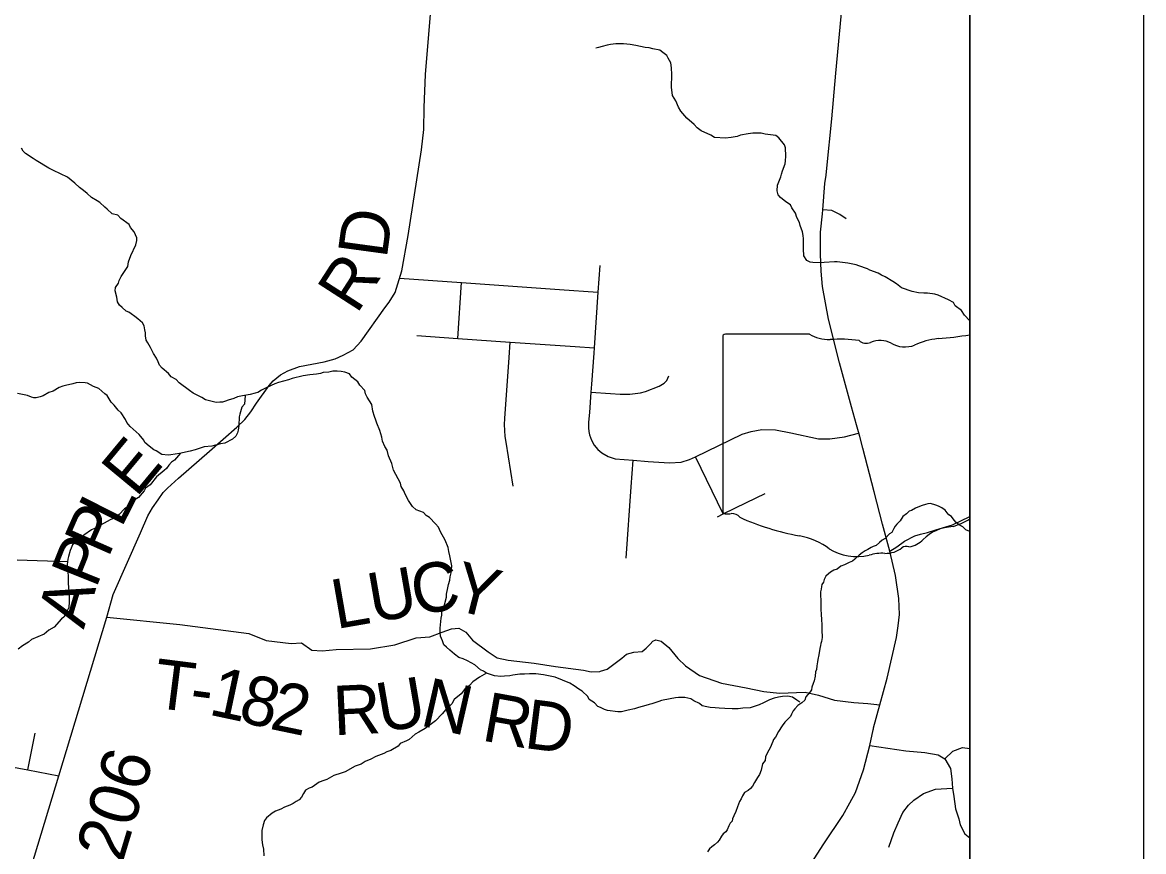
# Model space of a CAD drawing. Extents: x 0 to 34, y 0 to 22.
# Drawn here: x 8.355 to 9, y 14.464 to 14.941 of the extents above; entities that cross this region are included whole.
import ezdxf

# ---------------------------------------------------------------- set-up
doc = ezdxf.new("R2010")
doc.units = 0
for name, color, linetype in [('GM_X_Corporation', 7, 'Continuous'), ('GM_X_Corporation_Text', 7, 'Continuous'), ('GM_X_Minor_River', 7, 'Continuous'), ('GM_X_State_Location', 7, 'Continuous'), ('GM_X_State_Route', 7, 'Continuous'), ('GM_X_Township_Road', 7, 'Continuous'), ('GM_X_Township_Road_Text', 7, 'Continuous'), ('SH_Cut_Line', 7, 'Continuous'), ('SH_Data', 7, 'Continuous')]:
    doc.layers.add(name, color=color, linetype=linetype)

msp = doc.modelspace()

# ---------------------------------------------------------------- linework, layer by layer
at = {"layer": 'GM_X_Corporation'}
msp.add_lwpolyline([(8.31297, 14.1), (8.9, 14.1), (8.9, 17.02104)], dxfattribs=at)
at = {"layer": 'GM_X_Corporation_Text'}
for p, q in [((8.8078, 14.76211), (8.75951, 14.76211)), ((8.9, 14.65569), (8.9, 14.76171)), ((8.75792, 14.76037), (8.75792, 14.66033))]:
    msp.add_line(p, q, dxfattribs=at)
for centre, major_axis, start_param, end_param in [((8.75981, 14.7606), (0.00191, 0), 1.727492, 3.291633), ((8.81929, 14.77372), (0.01852, 0), 4.042888, 4.731792), ((8.86401, 14.89852), (0.17476, 0), 4.814394, 4.919827), ((8.82543, 14.70593), (0.06648, 0), 1.404758, 1.657859), ((8.84052, 14.76112), (0.00534, 0), 3.836095, 5.185415), ((8.84837, 14.74955), (0.01111, 0), 0.950623, 2.079405), ((8.8627, 14.76541), (0.01336, 0), 4.08156, 5.145723), ((8.8863, 14.73155), (0.03516, 0), 1.699012, 2.107814), ((8.75982, 14.66011), (0.00193, 0), 2.993084, 4.5083), ((8.76011, 14.67034), (0.0147, 0), 4.665946, 4.897461), ((8.76312, 14.65455), (0.0053, 0), 0.519207, 1.627899), ((8.83003, 14.74445), (0.1262, 0), 4.195997, 4.488961), ((8.8738, 14.68368), (0.04371, 0), 5.101753, 5.355196), ((8.79241, 14.61537), (0.03949, 0), 0.823519, 1.323587), ((8.89223, 14.63223), (0.02394, 0), 1.647645, 2.488434), ((8.85142, 14.64656), (0.01335, 0), 4.691044, 5.507374), ((8.8635, 14.63687), (0.00376, 0), 1.147584, 2.315152), ((8.8619, 14.65063), (0.01412, 0), 4.937069, 5.64225), ((8.83512, 14.65406), (0.02506, 0), 4.026481, 4.996735), ((8.84959, 14.61946), (0.02059, 0), 1.495662, 1.94098)]:
    msp.add_ellipse(centre, major_axis=major_axis, ratio=0.8, start_param=start_param, end_param=end_param, dxfattribs=at)
at = {"layer": 'GM_X_Minor_River'}
for points in [[(8.70473, 14.92874), (8.70094, 14.92919), (8.69637, 14.92908), (8.69332, 14.92875), (8.69142, 14.92841), (8.68855, 14.92751), (8.68645, 14.92698), (8.68493, 14.92662)], [(8.9, 14.76972), (8.89695, 14.77288), (8.89528, 14.77557), (8.89172, 14.7783), (8.89061, 14.78022), (8.88779, 14.78179), (8.88194, 14.78456), (8.87986, 14.78497), (8.87568, 14.78562), (8.87359, 14.78565), (8.87056, 14.7859), (8.86695, 14.78653), (8.86072, 14.78873), (8.85791, 14.79106), (8.85584, 14.79224), (8.85132, 14.79498), (8.84925, 14.79597), (8.84736, 14.79714), (8.84264, 14.79894), (8.84113, 14.79953), (8.83622, 14.80133), (8.83471, 14.80193), (8.82997, 14.80296), (8.82371, 14.80364), (8.82219, 14.80367), (8.81629, 14.8032), (8.8142, 14.80305), (8.80983, 14.80332), (8.80831, 14.80353), (8.80624, 14.80433), (8.80457, 14.80702), (8.80445, 14.81121), (8.80436, 14.81691), (8.8042, 14.81882), (8.80385, 14.82091), (8.80239, 14.82455), (8.80204, 14.82627), (8.80057, 14.82915), (8.79985, 14.83163), (8.79762, 14.83471), (8.79689, 14.83644), (8.79426, 14.83819), (8.79107, 14.84072), (8.78977, 14.84226), (8.78923, 14.84456), (8.78948, 14.84778), (8.79127, 14.8525), (8.79168, 14.85402), (8.79228, 14.8561), (8.79387, 14.86006), (8.79409, 14.86177), (8.79432, 14.86443), (8.79402, 14.86919), (8.79348, 14.87091), (8.79013, 14.87496), (8.78844, 14.87632), (8.78237, 14.87719), (8.78009, 14.87761), (8.77516, 14.87769), (8.77249, 14.87736), (8.7681, 14.87649), (8.76619, 14.87576), (8.76276, 14.87525), (8.75952, 14.87474), (8.75325, 14.87523), (8.751, 14.8766), (8.74552, 14.87898), (8.74327, 14.88073), (8.74159, 14.88266), (8.73728, 14.88635), (8.73393, 14.8904), (8.73245, 14.8927), (8.73099, 14.89634), (8.72895, 14.89942), (8.72846, 14.90418), (8.72858, 14.9114), (8.72845, 14.91521), (8.72812, 14.91807), (8.72646, 14.92076), (8.72572, 14.92229), (8.72347, 14.92404), (8.72178, 14.9254), (8.7178, 14.92623), (8.71553, 14.92684), (8.71326, 14.92707), (8.70795, 14.92812), (8.70473, 14.92874)], [(8.40675, 14.83133), (8.40394, 14.83404), (8.40244, 14.83502), (8.39963, 14.83773), (8.39813, 14.83871), (8.39493, 14.84066), (8.39231, 14.84299), (8.39025, 14.84474), (8.388, 14.84649), (8.38519, 14.84901), (8.38106, 14.85232), (8.37295, 14.85626), (8.37031, 14.85764), (8.36297, 14.86195), (8.36128, 14.86312), (8.35696, 14.86605), (8.35546, 14.86741), (8.35454, 14.86913)], [(8.57714, 14.66633), (8.57531, 14.66998), (8.57458, 14.67189), (8.57291, 14.67439), (8.57256, 14.6763), (8.57127, 14.67879), (8.5685, 14.68379), (8.56762, 14.68761), (8.5656, 14.69201), (8.5649, 14.69526), (8.5636, 14.69737), (8.56232, 14.70044), (8.56179, 14.70273), (8.56071, 14.70655), (8.55907, 14.71076), (8.55834, 14.71249), (8.55762, 14.71459), (8.55672, 14.71765), (8.55602, 14.72165), (8.55343, 14.72569), (8.55251, 14.72761), (8.55216, 14.72952), (8.54918, 14.73261), (8.54807, 14.73453), (8.54469, 14.73726), (8.5432, 14.73918), (8.54056, 14.74018), (8.53848, 14.7406), (8.5362, 14.74083), (8.53372, 14.74068), (8.53143, 14.74015), (8.5282, 14.74002), (8.52648, 14.73948), (8.52419, 14.73895), (8.52038, 14.73863), (8.51657, 14.73813), (8.51027, 14.73653), (8.50817, 14.73581), (8.50244, 14.7342), (8.50034, 14.73347), (8.49823, 14.73256), (8.49536, 14.73109), (8.49267, 14.72981), (8.49056, 14.72851), (8.48903, 14.72816), (8.48617, 14.72726), (8.48178, 14.72657), (8.47892, 14.72606), (8.47681, 14.72495), (8.47338, 14.72406), (8.47185, 14.72352), (8.47013, 14.72298), (8.4686, 14.72281), (8.46651, 14.72266), (8.46046, 14.72429), (8.45839, 14.72566), (8.4533, 14.72803), (8.45123, 14.72958), (8.44522, 14.73406), (8.44354, 14.736), (8.44072, 14.73757), (8.43923, 14.7393), (8.43548, 14.74241), (8.43399, 14.74415), (8.43326, 14.74606), (8.43215, 14.74817), (8.43049, 14.75087), (8.42884, 14.75432), (8.42717, 14.75701), (8.42625, 14.75855), (8.42591, 14.76102), (8.42594, 14.76273), (8.42559, 14.76445), (8.42524, 14.76674), (8.42413, 14.76847), (8.42151, 14.7708), (8.41982, 14.77216), (8.41776, 14.77372), (8.41625, 14.77469), (8.41474, 14.77529), (8.4125, 14.77742), (8.411, 14.77878), (8.40989, 14.7807), (8.40937, 14.78337), (8.40848, 14.787), (8.4087, 14.7889), (8.41045, 14.79134), (8.41086, 14.79285), (8.41184, 14.79512), (8.41574, 14.80094), (8.41617, 14.8036), (8.41756, 14.80737), (8.42032, 14.81341), (8.42094, 14.81587), (8.42096, 14.81739), (8.41931, 14.82084), (8.41726, 14.82335), (8.41653, 14.82507), (8.41165, 14.82858), (8.40997, 14.83051), (8.40675, 14.83133)], [(8.48331, 14.72681), (8.48284, 14.7218), (8.48129, 14.71993), (8.48009, 14.71596), (8.47987, 14.71444), (8.4796, 14.7095), (8.47917, 14.70685), (8.47877, 14.70533), (8.47797, 14.70325), (8.47604, 14.70158), (8.47163, 14.69937), (8.46915, 14.69885), (8.464, 14.69761), (8.45962, 14.69711), (8.45446, 14.69549), (8.4516, 14.69478), (8.44549, 14.69337), (8.44053, 14.6925), (8.43901, 14.69234), (8.43522, 14.69279), (8.43202, 14.69494), (8.4307, 14.69553), (8.42807, 14.69767), (8.42545, 14.69962), (8.4249, 14.70096), (8.42229, 14.70424), (8.41705, 14.70889), (8.41519, 14.7112), (8.41445, 14.71293), (8.41186, 14.71678), (8.41017, 14.71833), (8.40794, 14.72122), (8.40626, 14.72296), (8.40385, 14.72681), (8.40254, 14.72778), (8.39898, 14.7307), (8.39595, 14.73189), (8.39257, 14.73385), (8.39124, 14.73406), (8.38801, 14.73431), (8.3861, 14.73396), (8.38419, 14.73343), (8.37981, 14.73255), (8.37828, 14.73201), (8.37618, 14.73129), (8.37272, 14.72926), (8.37024, 14.72854), (8.36697, 14.7265), (8.36525, 14.72597), (8.36296, 14.72543), (8.36163, 14.72546), (8.36031, 14.72586), (8.35804, 14.72666), (8.35236, 14.7279)], [(8.4461, 14.69351), (8.44257, 14.68943), (8.44084, 14.68832), (8.43929, 14.68663), (8.43793, 14.68475), (8.43658, 14.68364), (8.43234, 14.67991), (8.42865, 14.67541), (8.42595, 14.67337), (8.42517, 14.67186), (8.42187, 14.66811), (8.41995, 14.66682), (8.41666, 14.66326), (8.41378, 14.6616), (8.41068, 14.65823), (8.4078, 14.65619), (8.40569, 14.65528), (8.40396, 14.65417), (8.39994, 14.65215), (8.39667, 14.65011), (8.39495, 14.64938), (8.39053, 14.64642), (8.38898, 14.64473), (8.38397, 14.64083), (8.38318, 14.63894), (8.38258, 14.63762), (8.38157, 14.63402), (8.38117, 14.63251), (8.38093, 14.62947), (8.38106, 14.62624), (8.38139, 14.62319), (8.38151, 14.619), (8.38165, 14.61615), (8.38181, 14.61424), (8.38192, 14.60968), (8.38208, 14.60796), (8.38184, 14.60474), (8.38105, 14.60323), (8.3789, 14.59927), (8.37755, 14.59816), (8.37329, 14.59348), (8.3704, 14.59163), (8.36771, 14.58939), (8.36043, 14.58629), (8.35869, 14.58479), (8.35524, 14.58276), (8.35273, 14.58072)], [(8.80235, 14.55036), (8.80065, 14.55134), (8.79802, 14.5531), (8.79537, 14.55372), (8.79233, 14.55358), (8.79004, 14.55324), (8.78756, 14.55253), (8.78488, 14.55162), (8.78143, 14.54997), (8.77894, 14.54868), (8.77378, 14.54706), (8.76959, 14.54676), (8.76673, 14.54643), (8.76331, 14.54649), (8.75913, 14.54656), (8.75591, 14.54681), (8.75363, 14.54704), (8.75078, 14.54728), (8.74888, 14.5475), (8.74604, 14.54812), (8.74455, 14.54948), (8.74134, 14.55106), (8.73965, 14.55223), (8.73605, 14.55305), (8.73244, 14.55293), (8.73072, 14.55277), (8.72767, 14.55225), (8.72271, 14.5512), (8.72118, 14.55065), (8.71717, 14.54939), (8.71564, 14.54885), (8.71373, 14.54831), (8.70953, 14.54724), (8.70724, 14.54652), (8.70361, 14.54564), (8.6998, 14.54475), (8.69752, 14.54479), (8.69163, 14.54547), (8.68993, 14.54607), (8.68767, 14.54725), (8.68616, 14.54785), (8.68411, 14.54997), (8.68109, 14.55174), (8.68036, 14.55346), (8.67699, 14.55656), (8.67511, 14.55774), (8.67248, 14.55969), (8.67004, 14.56125), (8.6657, 14.56285), (8.66154, 14.56463), (8.65491, 14.56608), (8.65036, 14.56654), (8.64675, 14.56661), (8.6439, 14.56647), (8.64123, 14.56632), (8.63723, 14.56582), (8.63552, 14.56547), (8.63247, 14.56515), (8.63037, 14.56499), (8.62658, 14.56544), (8.62205, 14.56704), (8.62035, 14.56802), (8.61865, 14.56881), (8.61528, 14.57172), (8.61114, 14.57408), (8.60869, 14.57526), (8.60623, 14.57588), (8.6036, 14.57782), (8.60098, 14.58015), (8.59911, 14.5819), (8.59742, 14.58326), (8.5967, 14.58555), (8.5956, 14.58823), (8.59545, 14.59033), (8.59549, 14.5928), (8.59597, 14.59868), (8.59638, 14.60039), (8.5964, 14.6021), (8.59778, 14.60493), (8.59801, 14.60702), (8.59902, 14.61061), (8.59905, 14.61251), (8.59987, 14.61611), (8.60028, 14.618), (8.60089, 14.62047), (8.60112, 14.62236), (8.60172, 14.62463), (8.60218, 14.62881), (8.60094, 14.63454), (8.60041, 14.63702), (8.60007, 14.63931), (8.59824, 14.64352), (8.59566, 14.64832), (8.59438, 14.651), (8.5927, 14.65294), (8.58934, 14.65661), (8.58726, 14.6576), (8.58577, 14.65933), (8.58162, 14.66093), (8.57956, 14.66287), (8.57714, 14.66633)], [(8.9, 14.64847), (8.89999, 14.64848), (8.89773, 14.64947), (8.89604, 14.65121), (8.89491, 14.6518), (8.89341, 14.65278), (8.89228, 14.65356), (8.89097, 14.65491), (8.88949, 14.65703), (8.88798, 14.658), (8.88705, 14.65916), (8.88594, 14.6607), (8.88387, 14.66207), (8.88199, 14.66306), (8.88048, 14.66365), (8.87934, 14.66405), (8.87726, 14.66466), (8.87593, 14.66449), (8.87459, 14.66395), (8.87268, 14.66341), (8.87115, 14.66286), (8.86885, 14.66195), (8.86655, 14.66047), (8.86521, 14.66012), (8.86366, 14.65862), (8.86155, 14.65714), (8.85999, 14.65469), (8.85805, 14.65264), (8.85708, 14.65151), (8.8563, 14.6502), (8.85512, 14.64794), (8.85378, 14.6472), (8.85145, 14.64439), (8.84972, 14.64347), (8.84818, 14.64216), (8.84625, 14.64049), (8.84453, 14.63976), (8.84338, 14.6392), (8.84146, 14.6381), (8.83993, 14.63736), (8.8382, 14.63625), (8.83646, 14.63495), (8.83395, 14.63252), (8.8326, 14.63141), (8.83069, 14.63068), (8.828, 14.62921), (8.8259, 14.62848), (8.82378, 14.62681), (8.82187, 14.62627), (8.81995, 14.62498), (8.81879, 14.62405), (8.81725, 14.62274), (8.81627, 14.62086), (8.81586, 14.61934), (8.81489, 14.61803), (8.81468, 14.61689), (8.81447, 14.61537), (8.81425, 14.61367), (8.8142, 14.61101), (8.81437, 14.60948), (8.81433, 14.60758), (8.81429, 14.60473), (8.81445, 14.60321), (8.81461, 14.6013), (8.81473, 14.59731), (8.81489, 14.5954), (8.81486, 14.59369), (8.815, 14.59065), (8.81515, 14.58855), (8.81513, 14.58741), (8.81472, 14.58514), (8.81432, 14.584)], [(8.38104, 14.63094), (8.35202, 14.63199)], [(8.81432, 14.584), (8.81411, 14.58286), (8.8137, 14.58116), (8.81326, 14.57756), (8.81264, 14.5749), (8.81243, 14.57339), (8.81201, 14.57111), (8.81178, 14.56902), (8.81138, 14.5677), (8.81115, 14.56523), (8.81054, 14.56258), (8.80994, 14.56107), (8.80914, 14.55899), (8.80893, 14.55728), (8.80815, 14.55616), (8.80679, 14.55466), (8.80582, 14.55335), (8.80522, 14.55145), (8.80348, 14.54996), (8.80117, 14.54829), (8.79943, 14.54642), (8.79846, 14.5453), (8.79748, 14.54341), (8.79688, 14.54209), (8.79514, 14.54022), (8.7936, 14.53873), (8.79204, 14.53666), (8.79009, 14.53347), (8.78832, 14.53007), (8.78716, 14.52876), (8.78676, 14.52763), (8.78518, 14.52404), (8.78361, 14.52122), (8.78262, 14.51876), (8.78239, 14.51668), (8.78084, 14.5148), (8.78002, 14.5112), (8.77902, 14.50856), (8.77785, 14.50687), (8.77629, 14.50404), (8.77511, 14.50197), (8.77395, 14.50066), (8.77259, 14.49935), (8.77048, 14.49825), (8.76931, 14.49637), (8.76852, 14.49467), (8.76755, 14.49317), (8.76635, 14.48996), (8.76555, 14.48731), (8.76437, 14.48486), (8.76358, 14.48316), (8.76337, 14.48183), (8.76221, 14.48071), (8.76142, 14.4792), (8.76043, 14.47675), (8.75965, 14.47562), (8.75811, 14.47451), (8.75714, 14.47319), (8.75596, 14.47093), (8.75499, 14.46962), (8.75325, 14.46813), (8.75171, 14.46701), (8.75036, 14.4659), (8.74919, 14.4642)], [(8.62205, 14.56704), (8.61801, 14.56464), (8.61417, 14.56204), (8.61223, 14.5598), (8.60934, 14.55756), (8.6074, 14.55513), (8.60354, 14.55177), (8.60217, 14.54932), (8.59869, 14.54596), (8.59656, 14.54353), (8.59269, 14.5396), (8.58672, 14.53514), (8.58307, 14.53293), (8.58097, 14.53182), (8.57749, 14.52884), (8.57596, 14.52811), (8.57232, 14.52646), (8.57134, 14.52496), (8.56712, 14.52237), (8.56464, 14.52165), (8.5631, 14.52073), (8.55832, 14.5191), (8.55544, 14.51744), (8.55219, 14.51616), (8.54988, 14.51468), (8.54644, 14.51341), (8.54068, 14.51009), (8.53839, 14.50937), (8.53418, 14.50811), (8.53015, 14.50571), (8.52843, 14.50517), (8.52576, 14.50427), (8.52172, 14.5013), (8.52, 14.50076), (8.51789, 14.49965), (8.51671, 14.49777), (8.51572, 14.49551), (8.51437, 14.49401), (8.51264, 14.49309), (8.51091, 14.49198), (8.509, 14.49106), (8.50593, 14.48978), (8.50382, 14.48868), (8.50076, 14.48759), (8.49885, 14.48649), (8.49557, 14.48369), (8.4944, 14.48219), (8.4936, 14.47973), (8.49279, 14.47651), (8.49291, 14.4729), (8.49288, 14.471), (8.49321, 14.46814), (8.49374, 14.46566), (8.49406, 14.46185)]]:
    msp.add_lwpolyline(points, dxfattribs=at)
at = {"layer": 'GM_X_State_Route'}
for points in [[(8.81734, 14.8536), (8.81784, 14.85755), (8.82064, 14.88595), (8.82293, 14.91216), (8.82717, 14.95733), (8.83017, 14.99041), (8.83248, 15.01422), (8.83471, 15.03475), (8.83782, 15.07704), (8.84166, 15.12668), (8.84404, 15.16121), (8.84636, 15.19646), (8.84879, 15.22757), (8.8494, 15.23637), (8.85025, 15.24269), (8.85198, 15.25089)], [(8.84457, 14.53492), (8.8447, 14.53541), (8.84834, 14.5487), (8.85254, 14.56401), (8.85781, 14.58745), (8.85875, 14.59418), (8.85954, 14.60081), (8.85924, 14.60988), (8.85724, 14.62313), (8.8541, 14.63714), (8.84977, 14.65261), (8.84497, 14.67132), (8.83854, 14.69652), (8.83671, 14.70322), (8.83488, 14.70993), (8.83209, 14.72029), (8.82502, 14.74552), (8.8188, 14.77073), (8.81541, 14.78941), (8.81459, 14.79837), (8.81416, 14.80807), (8.81416, 14.82063), (8.81527, 14.83126), (8.81554, 14.83362), (8.81673, 14.84865), (8.81734, 14.8536)], [(8.78446, 14.41939), (8.78678, 14.4231), (8.79981, 14.44345), (8.81615, 14.46868), (8.82694, 14.48499), (8.83103, 14.4924), (8.83426, 14.49828), (8.83891, 14.5113), (8.84254, 14.52533), (8.84444, 14.53444), (8.84457, 14.53492)]]:
    msp.add_lwpolyline(points, dxfattribs=at)
at = {"layer": 'GM_X_Township_Road'}
for p, q in [((8.68725, 14.80151), (8.68617, 14.78623)), ((8.60551, 14.75963), (8.60777, 14.7918)), ((8.66403, 14.78779), (8.68617, 14.78623)), ((8.68617, 14.78623), (8.68391, 14.75411)), ((8.63511, 14.74869), (8.63574, 14.7575)), ((8.67305, 14.75488), (8.68391, 14.75411)), ((8.75824, 14.65861), (8.74229, 14.69139)), ((8.70526, 14.67409), (8.70645, 14.68947)), ((8.70245, 14.63312), (8.70526, 14.67409)), ((8.35823, 14.51137), (8.36246, 14.53252))]:
    msp.add_line(p, q, dxfattribs=at)
for points in [[(8.40375, 14.59925), (8.40725, 14.61213), (8.42296, 14.64778), (8.42719, 14.65754), (8.42996, 14.66202), (8.43311, 14.66669), (8.43607, 14.67098), (8.43859, 14.67338), (8.44499, 14.67909), (8.46264, 14.69477), (8.47853, 14.70859), (8.483, 14.71284), (8.48653, 14.7173), (8.48969, 14.72234), (8.49696, 14.7324), (8.49931, 14.73518), (8.50357, 14.73868), (8.50779, 14.74085), (8.51449, 14.74333), (8.52876, 14.74619), (8.53506, 14.74792), (8.53966, 14.74989), (8.54535, 14.75294), (8.55005, 14.75795), (8.56367, 14.77716), (8.56603, 14.78052), (8.56955, 14.78594), (8.5733, 14.79847), (8.57704, 14.81876), (8.58461, 14.86803), (8.58601, 14.87987), (8.58618, 14.89241), (8.58688, 14.91138), (8.59218, 14.97389)], [(8.82899, 14.82844), (8.82534, 14.83084), (8.82072, 14.83322), (8.81554, 14.83362)], [(8.57205, 14.79429), (8.60777, 14.7918), (8.66403, 14.78779)], [(8.58204, 14.76128), (8.60551, 14.75963), (8.63574, 14.7575), (8.67305, 14.75488)], [(8.63744, 14.67465), (8.63329, 14.6998), (8.63283, 14.70323), (8.63256, 14.70668), (8.6325, 14.71014), (8.63265, 14.71359), (8.63511, 14.74869)], [(8.68391, 14.75411), (8.68374, 14.75104), (8.6824, 14.73334), (8.68206, 14.72861)], [(8.68206, 14.72861), (8.69334, 14.72793), (8.69887, 14.72742), (8.70448, 14.72743), (8.71071, 14.72835), (8.71357, 14.72907), (8.72139, 14.7322), (8.72423, 14.73379), (8.72577, 14.73544), (8.72701, 14.73807)], [(8.68206, 14.72861), (8.68121, 14.71695), (8.68081, 14.71141), (8.6807, 14.70821), (8.6809, 14.70609), (8.68134, 14.70401), (8.68248, 14.70098), (8.684, 14.69825), (8.68619, 14.69564), (8.68841, 14.69369), (8.69209, 14.69158), (8.69615, 14.69034), (8.70645, 14.68947)], [(8.74229, 14.69139), (8.7692, 14.70439), (8.77428, 14.70605), (8.7805, 14.70709), (8.78822, 14.70701), (8.7971, 14.70525), (8.81294, 14.70178), (8.81963, 14.70186), (8.8279, 14.70296), (8.83597, 14.70505)], [(8.70645, 14.68947), (8.71506, 14.68885), (8.72726, 14.688), (8.73395, 14.68846), (8.73878, 14.68982), (8.74229, 14.69139)], [(8.75483, 14.65695), (8.75824, 14.65861), (8.77153, 14.66508), (8.78238, 14.67035)], [(8.88047, 14.64943), (8.89006, 14.65236), (8.9, 14.65719)], [(8.8541, 14.63714), (8.85812, 14.63969), (8.86245, 14.64294), (8.86841, 14.64603), (8.87165, 14.64696), (8.87568, 14.64797), (8.88047, 14.64943)], [(8.33639, 14.34667), (8.33884, 14.36494), (8.34137, 14.37939), (8.34327, 14.38794), (8.34493, 14.39958), (8.34707, 14.4105), (8.35158, 14.42618), (8.35704, 14.44518), (8.36206, 14.4616), (8.3761, 14.50793), (8.40375, 14.59925)], [(8.40375, 14.59925), (8.44572, 14.59489), (8.48541, 14.58985), (8.49526, 14.58566), (8.50979, 14.5841), (8.51571, 14.58445), (8.52163, 14.5801), (8.52757, 14.57974), (8.53566, 14.58051), (8.55535, 14.58096), (8.5693, 14.58328), (8.5816, 14.58727), (8.58942, 14.58793), (8.59651, 14.59052), (8.60201, 14.59248), (8.60607, 14.59284), (8.61012, 14.59052), (8.6141, 14.58589), (8.62304, 14.57916), (8.62814, 14.57578), (8.6346, 14.57436), (8.64944, 14.57268), (8.66171, 14.57072), (8.6779, 14.56866), (8.6823, 14.56781), (8.68719, 14.56799), (8.68762, 14.56812)], [(8.68762, 14.56812), (8.69146, 14.56928), (8.69996, 14.57564), (8.70263, 14.57796), (8.70673, 14.57907), (8.71154, 14.5794), (8.71398, 14.58125), (8.71616, 14.58356), (8.71781, 14.58534), (8.71942, 14.58613), (8.72252, 14.58536), (8.72697, 14.5817), (8.73209, 14.57533), (8.73645, 14.57119), (8.74466, 14.56563), (8.75732, 14.56122), (8.7714, 14.55847), (8.78148, 14.55647), (8.79065, 14.55552), (8.80544, 14.55609), (8.813, 14.55432), (8.82217, 14.55145), (8.83337, 14.55015), (8.84148, 14.54942), (8.84834, 14.5487)], [(8.84254, 14.52533), (8.86318, 14.52225), (8.8741, 14.52125), (8.88177, 14.5199)], [(8.88574, 14.51764), (8.89034, 14.52216), (8.89585, 14.52423), (8.9, 14.52362)], [(8.88177, 14.5199), (8.88574, 14.51764), (8.8889, 14.51205), (8.8898, 14.50618), (8.89016, 14.50077), (8.8908, 14.49598), (8.89179, 14.48894), (8.89368, 14.48308), (8.89442, 14.47974), (8.89717, 14.47457), (8.9, 14.47212)], [(8.32692, 14.48557), (8.32907, 14.49738), (8.33107, 14.50261), (8.33322, 14.50647), (8.33608, 14.50912), (8.33987, 14.51155), (8.34366, 14.5128), (8.34789, 14.51316), (8.35823, 14.51137), (8.3761, 14.50793)], [(8.85343, 14.46683), (8.85632, 14.47513), (8.85885, 14.48082), (8.86155, 14.48678), (8.86471, 14.49093), (8.86778, 14.49391), (8.8734, 14.49768), (8.88024, 14.50023), (8.89016, 14.50077)]]:
    msp.add_lwpolyline(points, dxfattribs=at)
at = {"layer": 'SH_Cut_Line'}
msp.add_lwpolyline([(5.60301, 15.02173), (5.5402, 14.5449), (5.49472, 14.18022), (5.49031, 14.14478), (5.48934, 14.13697), (5.48791, 14.12545), (5.48474, 14.1), (8.9, 14.1), (8.9, 20.9)], dxfattribs=at)
at = {"layer": 'SH_Data'}
for p, q in [((9, 21), (9, 14)), ((8.9, 20.9), (8.9, 14.1))]:
    msp.add_line(p, q, dxfattribs=at)

# ---------------------------------------------------------------- texts
at = {"layer": 'GM_X_State_Location'}
for s in ['s', 'r']:
    msp.add_text(s, height=0.0000947, dxfattribs=at).set_placement((8.83846, 14.7037))
msp.add_text('132', height=0.0000947, rotation=0.00001, dxfattribs=at).set_placement((8.80503, 14.69681))
at = {"layer": 'GM_X_Township_Road_Text'}
for s, height, rotation, p in [('D', 0.02841, 82.24493, (8.56461, 14.80502)), ('R', 0.02841, 57.17706, (8.54738, 14.773)), ('E', 0.02841, 50.32612, (8.42055, 14.66746)), ('L', 0.02841, 63.31036, (8.41194, 14.6499)), ('P', 0.02841, 66.22179, (8.40437, 14.6327)), ('P', 0.02841, 68.12976, (8.39733, 14.61514)), ('U', 0.02841, 9.87735, (8.55655, 14.59593)), ('C', 0.02841, 9.32629, (8.5811, 14.6002)), ('Y', 0.02841, 345.73758, (8.60106, 14.60412)), ('L', 0.02841, 9.88435, (8.53561, 14.59228)), ('A', 0.02841, 73.30703, (8.39037, 14.59184)), ('T', 0.02841, 352.85, (8.42953, 14.5473)), ('1', 0.02841, 347.98993, (8.46155, 14.54324)), ('8', 0.02841, 345.73532, (8.47838, 14.53966)), ('2', 0.02841, 348.23924, (8.49666, 14.53505)), ('U', 0.02841, 9.76437, (8.56146, 14.53269)), ('N', 0.02841, 347.06027, (8.58314, 14.53701)), ('-', 0.02841, 352.4848, (8.45057, 14.54467)), ('R', 0.02841, 2.63535, (8.53438, 14.53121)), ('R', 0.02841, 349.80447, (8.61859, 14.52836)), ('D', 0.02841, 352.77227, (8.64312, 14.52399)), ('T-206', 0.028409, 73.22213, (8.40226, 14.42291))]:
    msp.add_text(s, height=height, rotation=rotation, dxfattribs=at).set_placement(p)

doc.saveas('drawing.dxf')
